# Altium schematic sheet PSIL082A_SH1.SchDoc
size 558 x 431 mm; Date: Not shown in title block; ApprovedBy: Not shown in title block; CheckedBy: Not shown in title block; Author: Not shown in title block; CompanyName: Not shown in title block; Engineer: Not shown in title block; Organization: Not shown in title block; Address1: Not shown in title block; Address2: Not shown in title block; Address3: Not shown in title block; Address4: Not shown in title block; DocumentNumber: 1; Revision: Use project parameter SCH_Rev; SheetNumber: 1; SheetTotal: 2; PageSetup: Record=PageOptions¦CenterHorizontal=True¦CenterVertical=True¦PrintScale=1.00¦XCorrection=1.00¦YCorrection=1.00¦PrintKind=0¦BorderSize=5000000¦LeftOffset=0¦BottomOffset=0¦Orientation=2¦PaperLength=1000¦PaperWidth=1000¦Scale=100¦PaperSource=15¦PrintQuality=600¦MediaType=1¦DitherType=10¦PaperKind=Letter¦PrintScaleMode=1
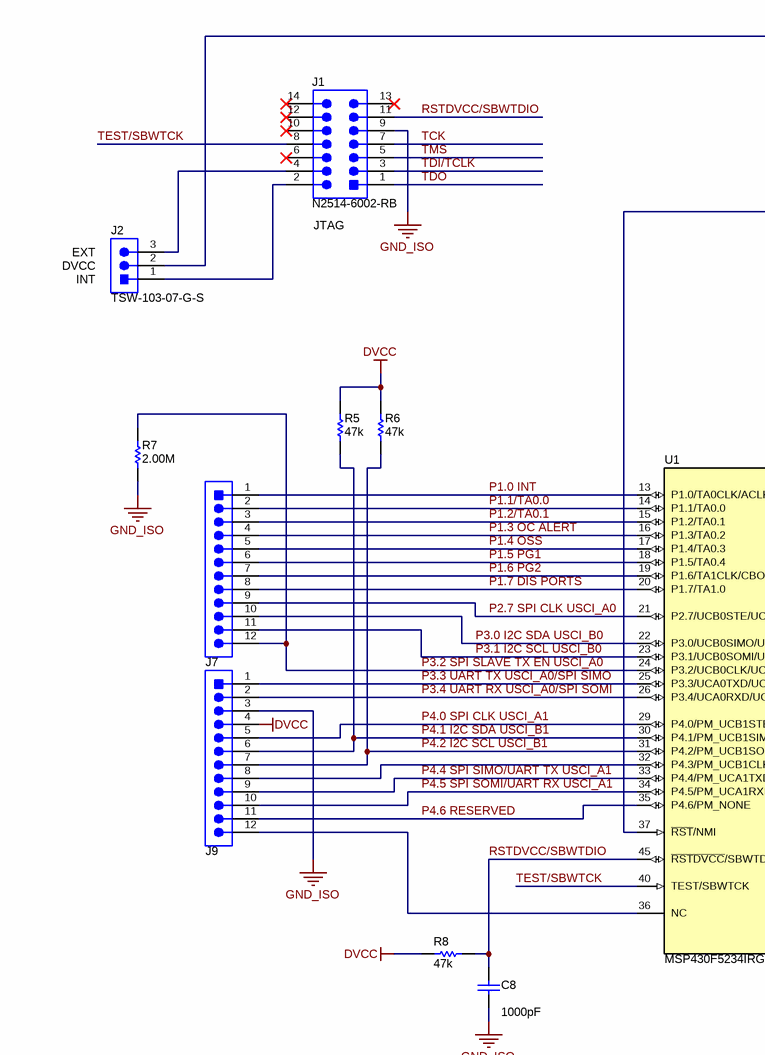
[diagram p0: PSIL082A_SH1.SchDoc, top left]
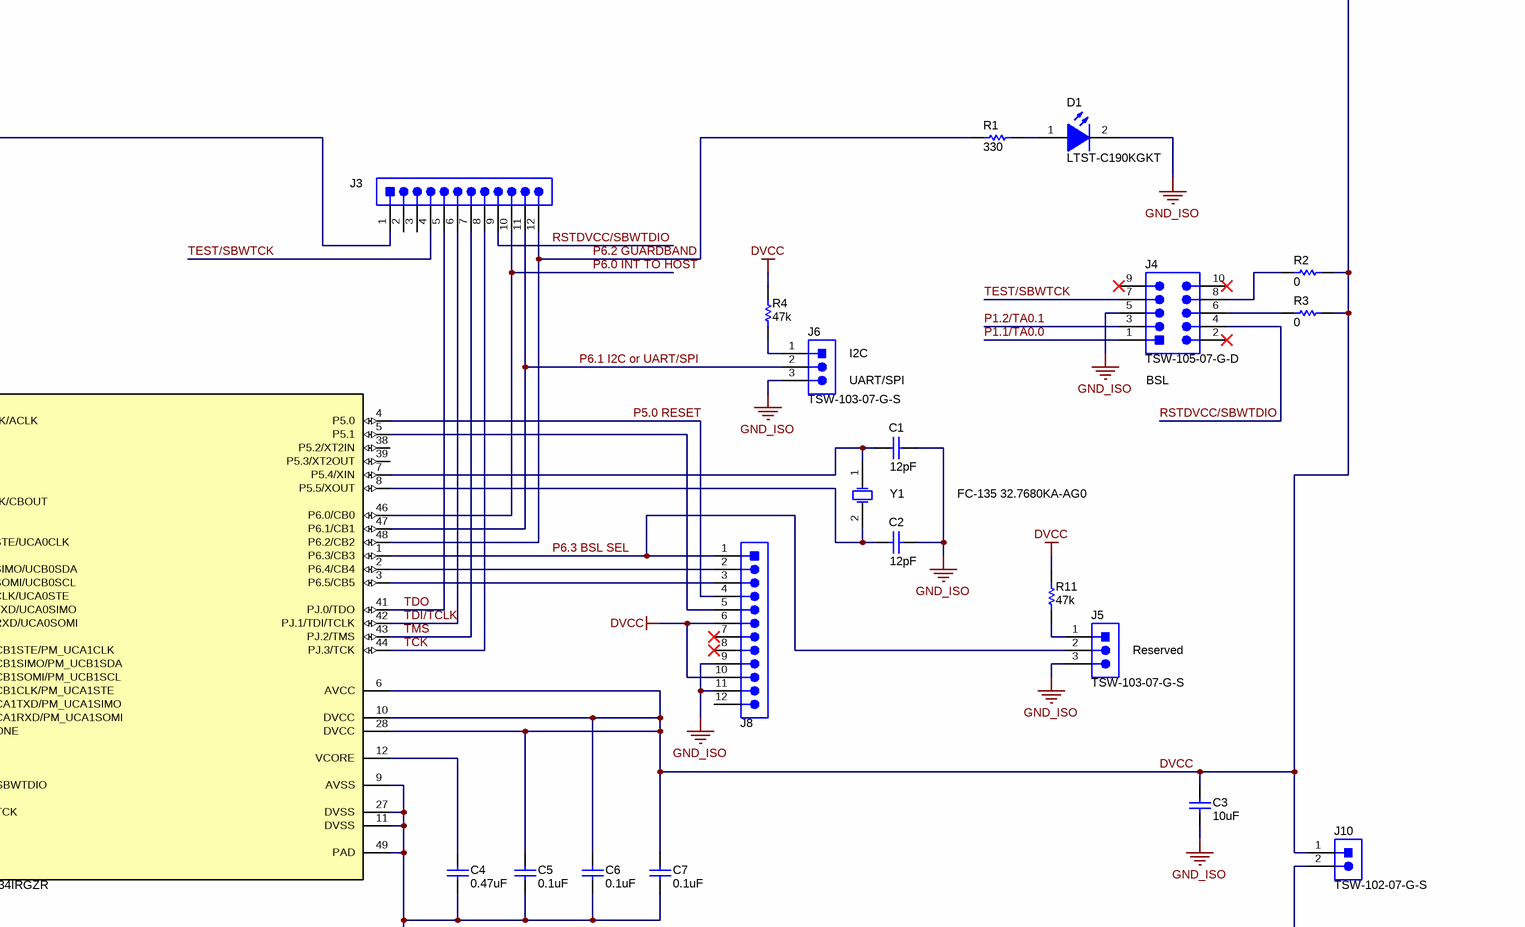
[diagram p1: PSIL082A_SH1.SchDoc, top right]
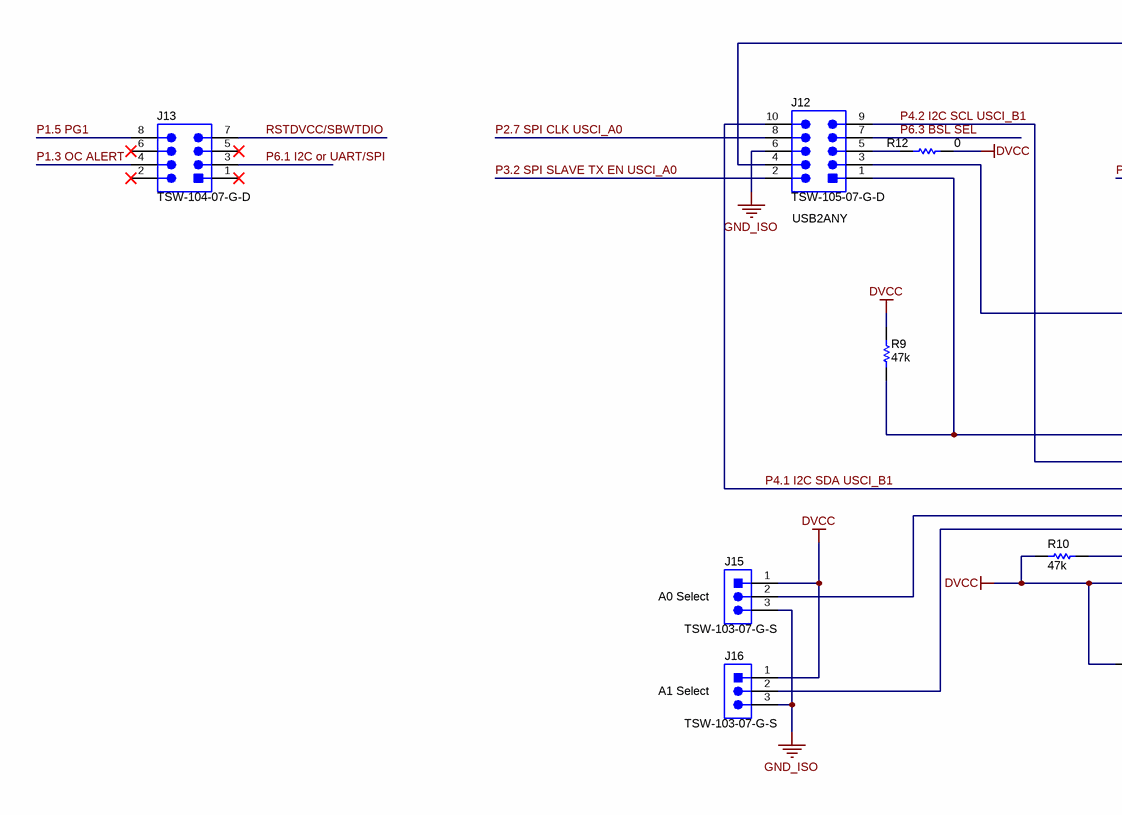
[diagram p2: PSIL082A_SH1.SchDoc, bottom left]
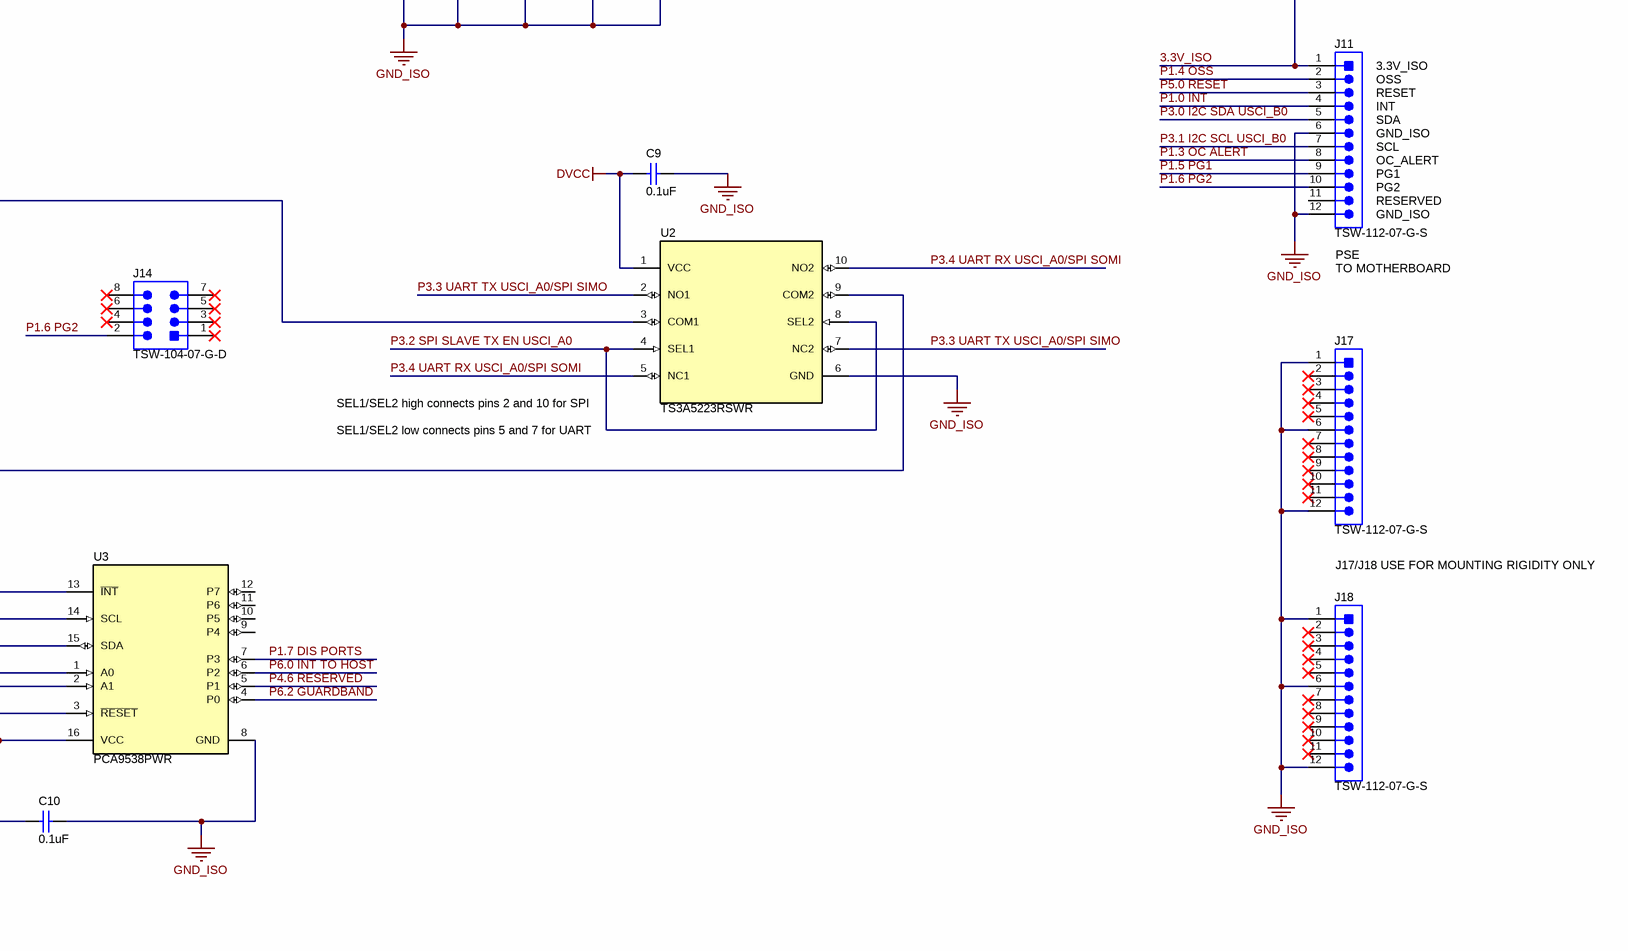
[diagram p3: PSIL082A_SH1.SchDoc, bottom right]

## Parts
C1  ValueDisplayed: 12pF  [0402L]  (hidden comment: CL05C120JB5NNNC)
C2  ValueDisplayed: 12pF  [0402L]  (hidden comment: CL05C120JB5NNNC)
C3  ValueDisplayed: 10uF  [0805L]  (hidden comment: 885012207026)
C4  ValueDisplayed: 0.47uF  [0603L]  (hidden comment: GCM188R71C474KA55D)
C5  ValueDisplayed: 0.1uF  [0603L]  (hidden comment: 885012206046)
C6  ValueDisplayed: 0.1uF  [0603L]  (hidden comment: 885012206046)
C7  ValueDisplayed: 0.1uF  [0603L]  (hidden comment: 885012206046)
C8  ValueDisplayed: 1000pF  [0603L]  (hidden comment: 885012206083)
C9  ValueDisplayed: 0.1uF  [0603L]  (hidden comment: 885012206046)
C10  ValueDisplayed: 0.1uF  [0603L]  (hidden comment: 885012206046)
D1  LTST-C190KGKT  [LED_LTST-C190_G]
J1  N2514-6002-RB  [3M_x2514-60xx]
J2  TSW-103-07-G-S  [TSW-103-07-G-S]
J3  TSW-112-07-G-S  [TSW-112-07-G-S]  (value not drawn)
J4  TSW-105-07-G-D  [TSW-105-07-G-D]
J5  TSW-103-07-G-S  [TSW-103-07-G-S]
J6  TSW-103-07-G-S  [TSW-103-07-G-S]
J7  TSW-112-07-G-S  [TSW-112-07-G-S]  (value not drawn)
J8  TSW-112-07-G-S  [TSW-112-07-G-S]  (value not drawn)
J9  TSW-112-07-G-S  [TSW-112-07-G-S]  (value not drawn)
J10  TSW-102-07-G-S  [TSW-102-07-G-S]
J11  TSW-112-07-G-S  [TSW-112-07-G-S]
J12  TSW-105-07-G-D  [TSW-105-07-G-D]
J13  TSW-104-07-G-D  [TSW-104-07-G-D]
J14  TSW-104-07-G-D  [TSW-104-07-G-D]
J15  TSW-103-07-G-S  [TSW-103-07-G-S]
J16  TSW-103-07-G-S  [TSW-103-07-G-S]
J17  TSW-112-07-G-S  [TSW-112-07-G-S]
J18  TSW-112-07-G-S  [TSW-112-07-G-S]
R1  ValueDisplayed: 330  [0402L]  (hidden comment: CRCW0402330RJNED)
R2  ValueDisplayed: 0  [0402L]  (hidden comment: ERJ-2GE0R00X)
R3  ValueDisplayed: 0  [0402L]  (hidden comment: ERJ-2GE0R00X)
R4  ValueDisplayed: 47k  [0402L]  (hidden comment: CRCW040247K0JNED)
R5  ValueDisplayed: 47k  [0402L]  (hidden comment: CRCW040247K0JNED)
R6  ValueDisplayed: 47k  [0402L]  (hidden comment: CRCW040247K0JNED)
R7  ValueDisplayed: 2.00M  [0402L]  (hidden comment: CRCW04022M00FKED)
R8  ValueDisplayed: 47k  [0402L]  (hidden comment: CRCW040247K0JNED)
R9  ValueDisplayed: 47k  [0402L]  (hidden comment: CRCW040247K0JNED)
R10  ValueDisplayed: 47k  [0402L]  (hidden comment: CRCW040247K0JNED)
R11  ValueDisplayed: 47k  [0402L]  (hidden comment: CRCW040247K0JNED)
R12  ValueDisplayed: 0  [0402L]  (hidden comment: ERJ-2GE0R00X)
U1  MSP430F5234IRGZR  [RGZ0048A]
U2  TS3A5223RSWR  [RSW0010A]
U3  PCA9538PWR  [PW0016A_L]
Y1  FC-135 32.7680KA-AG0  [Epson_FC-135]

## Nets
DVCC: C3.2 C5.2 C6.2 C7.2 C9.2 C10.2 J2.2 J8.6 J8.10 J9.4 J10.1 J15.1 J16.1 R2.1 R3.1 R4.2 R5.2 R6.2 R8.1 R9.2 R10.2 R11.2 R12.1 U1.6(AVCC) U1.10(DVCC) U1.28(DVCC) U2.1(VCC) U3.16(VCC)
GND_ISO: C1.1 C2.1 C3.1 C4.1 C5.1 C6.1 C7.1 C8.2 C9.1 C10.1 D1.2(K) J1.9 J4.5 J5.3 J6.3 J8.9 J8.11 J9.3 J11.6 J11.12 J12.6 J15.3 J16.3 J17.1 J17.6 J17.12 J18.1 J18.6 J18.12 R7.2 U1.9(AVSS) U1.11(DVSS) U1.27(DVSS) U1.49(PAD) U2.6(GND) U3.8(GND)
3.3V_ISO: J10.2 J11.1
P1.0 INT: J7.1 J11.4 U1.13(P1.0/TA0CLK/ACLK)
P1.1/TA0.0: J4.1 J7.2 U1.14(P1.1/TA0.0)
P1.2/TA0.1: J4.3 J7.3 U1.15(P1.2/TA0.1)
P1.3 OC ALERT: J7.4 J11.8 J13.4 U1.16(P1.3/TA0.2)
P1.4 OSS: J7.5 J11.2 U1.17(P1.4/TA0.3)
P1.5 PG1: J7.6 J11.9 J13.8 U1.18(P1.5/TA0.4)
P1.6 PG2: J7.7 J11.10 J14.2 U1.19(P1.6/TA1CLK/CBOUT)
P1.7 DIS PORTS: J7.8 U1.20(P1.7/TA1.0) U3.7(P3)
P2.7 SPI CLK USCI_A0: J7.9 J12.8 U1.21(P2.7/UCB0STE/UCA0CLK)
P3.0 I2C SDA USCI_B0: J7.10 J11.5 U1.22(P3.0/UCB0SIMO/UCB0SDA)
P3.1 I2C SCL USCI_B0: J7.11 J11.7 U1.23(P3.1/UCB0SOMI/UCB0SCL)
P3.2 SPI SLAVE TX EN USCI_A0: J7.12 J12.2 R7.1 U1.24(P3.2/UCB0CLK/UCA0STE) U2.4(SEL1) U2.8(SEL2)
P3.3 UART TX USCI_A0/SPI SIMO: J9.1 U1.25(P3.3/UCA0TXD/UCA0SIMO) U2.2(NO1) U2.7(NC2)
P3.4 UART RX USCI_A0/SPI SOMI: J9.2 U1.26(P3.4/UCA0RXD/UCA0SOMI) U2.5(NC1) U2.10(NO2)
P4.0 SPI CLK USCI_A1: J9.5 U1.29(P4.0/PM_UCB1STE/PM_UCA1CLK)
P4.1 I2C SDA USCI_B1: J9.6 J12.10 R5.1 U1.30(P4.1/PM_UCB1SIMO/PM_UCB1SDA) U3.15(SDA)
P4.2 I2C SCL USCI_B1: J9.7 J12.9 R6.1 U1.31(P4.2/PM_UCB1SOMI/PM_UCB1SCL) U3.14(SCL)
P4.4 SPI SIMO/UART TX USCI_A1: J9.9 U1.33(P4.4/PM_UCA1TXD/PM_UCA1SIMO)
P4.5 SPI SOMI/UART RX USCI_A1: J9.10 U1.34(P4.5/PM_UCA1RXD/PM_UCA1SOMI)
P4.6 RESERVED: J9.11 U1.35(P4.6/PM_NONE) U3.5(P1)
P5.0 RESET: J8.4 J11.3 U1.4(P5.0)
P6.0 INT TO HOST: J3.10 U1.46(P6.0/CB0) U3.6(P2)
P6.1 I2C or UART/SPI: J3.11 J6.2 J13.3 U1.47(P6.1/CB1)
P6.2 GUARDBAND: J3.12 R1.1 U1.48(P6.2/CB2) U3.4(P0)
P6.3 BSL SEL: J5.2 J8.1 J12.7 U1.1(P6.3/CB3)
RSTDVCC/SBWTDIO: C8.1 J1.11 J3.9 J4.4 J13.7 R8.2 U1.45(~{RSTDVCC}/SBWTDIO)
TCK: J1.7 J3.8 U1.44(PJ.3/TCK)
TDI/TCLK: J1.3 J3.6 U1.42(PJ.1/TDI/TCLK)
TDO: J1.1 J3.5 U1.41(PJ.0/TDO)
TEST/SBWTCK: J1.8 J3.4 J4.7 U1.40(TEST/SBWTCK)
TMS: J1.5 J3.7 U1.43(PJ.2/TMS)
NetC1_2: C1.2 U1.7(P5.4/XIN) Y1.1(OSC1)
NetC2_2: C2.2 U1.8(P5.5/XOUT) Y1.2(OSC2)
NetC4_2: C4.2 U1.12(VCORE)
NetD1_1: D1.1(A) R1.2
NetJ1_2: J1.2 J2.1
NetJ1_4: J1.4 J2.3
NetJ3_1: J3.1 U1.37(~{RST}/NMI)
NetJ4_6: J4.6 R3.2
NetJ4_8: J4.8 R2.2
NetJ5_1: J5.1 R11.1
NetJ6_1: J6.1 R4.1
NetJ8_2: J8.2 U1.2(P6.4/CB4)
NetJ8_3: J8.3 U1.3(P6.5/CB5)
NetJ8_5: J8.5 U1.5(P5.1)
NetJ9_8: J9.8 U1.32(P4.3/PM_UCB1CLK/PM_UCA1STE)
NetJ9_12: J9.12 U1.36(NC)
NetJ12_1: J12.1 R9.1 U3.13(~{INT})
NetJ12_3: J12.3 U2.9(COM2)
NetJ12_4: J12.4 U2.3(COM1)
NetJ12_5: J12.5 R12.2
NetJ15_2: J15.2 U3.1(A0)
NetJ16_2: J16.2 U3.2(A1)
NetR10_1: R10.1 U3.3(~{RESET})

Not connected (* = marked no-connect by the designer): J1 6* 10* 12* 13* 14*; J3 2 3; J4 2* 9* 10*; J8 7* 8* 12; J11 11; J13 1* 2* 5* 6*; J14 1* 3* 4* 5* 6* 7* 8*; J17 2* 3* 4* 5* 7* 8* 9* 10* 11*; J18 2* 3* 4* 5* 7* 8* 9* 10* 11*; U1 38(P5.2/XT2IN) 39(P5.3/XT2OUT); U3 9(P4) 10(P5) 11(P6) 12(P7)

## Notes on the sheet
- (near J1) JTAG
- (near J2) EXT
- (near J2) INT
- (near J2) DVCC
- (near J6) I2C
- UART/SPI
- (near J4) BSL
- (near J5) Reserved
- (near J11) 3.3V_ISO
- (near J11) OSS
- (near J11) RESET
- (near J11) INT
- (near J11) SDA
- (near J11) GND_ISO
- (near J11) SCL
- (near J11) OC_ALERT
- (near J11) PG1
- (near J11) PG2
- (near J11) RESERVED
- (near J11) PSE
- (near J11) TO MOTHERBOARD
- (near J12) USB2ANY
- SEL1/SEL2 high connects pins 2 and 10 for SPI
- SEL1/SEL2 low connects pins 5 and 7 for UART
- J17/J18 USE FOR MOUNTING RIGIDITY ONLY
- (near J15) A0 Select
- (near J16) A1 Select

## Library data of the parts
C1 C2 = CMP-0006345-2: CAP, CERM, 12 pF, 50 V, +/- 5%, C0G/NP0, 0402; Manufacturer: Samsung Electro-Mechanics; TaMin_C: -55°C; Polarized: N; SizeAreaWB_mm2: 3; Value1: Unknown; U/M: EA; Value: 12pF; TaMax_C: 125°C; SizeZ_mm: 0.6; SizeX_mm: 1; SizeY_mm: 0.5; Cap_Case: 0402; Value2: 50V; CompType: Capacitor; AEC Category: Q200
C3 = CMP-0007691-2: CAP, CERM, 10 uF, 10 V, +/- 10%, X7R, 0805; Manufacturer: Wurth Elektronik; TaMin_C: -55°C; Polarized: N; SizeAreaWB_mm2: 6.75; Value1: Unknown; U/M: EA; Value: 10uF; TaMax_C: 125°C; SizeZ_mm: 1.45; SizeX_mm: 2; SizeY_mm: 1.25; Cap_Case: 0805; Value2: 10V; SizeArea_mm2: 2.5; CompType: Capacitor; Cap_F: 10µF; AEC Category: Q200
C4 = CMP-0007138-4: CAP, CERM, 0.47 uF, 16 V, +/- 10%, X7R, AEC-Q200 Grade 1, 0603; Manufacturer: MuRata; TaMin_C: -55°C; Polarized: N; SizeAreaWB_mm2: 4.68; Value1: Unknown; U/M: EA; Value: 0.47uF; TaMax_C: 125°C; SizeZ_mm: 1; SizeX_mm: 1.6; SizeY_mm: 0.8; Cap_Case: 0603; Value2: 16V; SizeArea_mm2: 1.28; CompType: Capacitor; AEC Qualified: Y; Cap_F: 470nF; AEC Category: Q200
C5-C7 C9 C10 = CMP-0006829-4: CAP, CERM, 0.1 uF, 16 V, +/- 10%, X7R, 0603; Manufacturer: Wurth Elektronik; TaMin_C: -55°C; Polarized: N; SizeAreaWB_mm2: 4.68; Value1: Unknown; U/M: EA; Value: 0.1uF; TaMax_C: 125°C; SizeZ_mm: 1; SizeX_mm: 1.6; SizeY_mm: 0.8; Cap_Case: 0603; Value2: 16V; SizeArea_mm2: 1.28; CompType: Capacitor; Cap_F: 100nF; AEC Category: Q200
C8 = CMP-0064933-4: CAP, CERM, 1000 pF, 50 V,+/- 10%, X7R, 0603; Manufacturer: Wurth Elektronik; TaMin_C: -55°C; Polarized: N; SizeAreaWB_mm2: 4.68; Value1: Unknown; U/M: EA; Value: 1000pF; TaMax_C: 125°C; SizeZ_mm: 1; SizeX_mm: 1.6; SizeY_mm: 0.8; Cap_Case: 0603; Value2: 50V; SizeArea_mm2: 1.28; CompType: Capacitor; Cap_F: 1nF; AEC Category: Q200
D1 = CMP-0002840-2: LED, Green, SMD; Manufacturer: Lite-On; Value1: W; Io_A: 30mA; Value2: 2V; Tjmax_C: 85°C; Type: AlInGaP
J1 = CMP-0075023-2: Header (shrouded), 100mil, 7x2, Gold, TH; Manufacturer: 3M; Green_Lifecycle: Active; Green_REACh: Passed
J2 J5 J6 J15 J16 = CMP-0075407-2: Header, 100mil, 3x1, Gold, TH; Manufacturer: Samtec; Pitch_mm: 2.54; Cert_VDE: N; Gender: Male; Cert_CSA: Y; Voltage_V: 550V; Green_REACh: Passed; Current_A: 6.3A; Green_Lifecycle: Active; Row_Count: 1
J3 J7-J9 J11 J17 J18 = CMP-0075424-1: Header, 100mil, 12x1, Gold, TH; Manufacturer: Samtec; Pitch_mm: 2.54; Cert_VDE: N; Gender: Male; Cert_CSA: Y; Current_A: 6.3A; Voltage_V: 550V; CT: False; Row_Count: 1; CNHeader: True
J4 = CMP-0075410-2: Header, 100mil, 5x2, Gold, TH; Manufacturer: Samtec; Current_A: 6.3A; Green_Lifecycle: Active; Shrouded: N; Gender: Male; Cert_CSA: Y; Green_REACh: Passed; Voltage_V: 550V; Row_Count: 2; RowSpacing_mm: 2.54
J10 = CMP-0075405-2: Header, 100mil, 2x1, Gold, TH; Manufacturer: Samtec; Pitch_mm: 2.54; Cert_VDE: N; Gender: Male; Cert_CSA: Y; Voltage_V: 550V; Green_REACh: Passed; Current_A: 6.3A; Green_Lifecycle: Active; Row_Count: 1
J12 = CMP-0075410-2: Header, 100mil, 5x2, Gold, TH; Manufacturer: Samtec; Green_Lifecycle: Active; Green_REACh: Passed; Cert_CSA: Y; Cert_CULUS: N; Current_A: 6.3A; Gender: Male; Pitch_mm: 2.54; Row_Count: 2; Voltage_V: 550V
J13 J14 = CMP-0075408-2: Header, 100mil, 4x2, Gold, TH; Manufacturer: Samtec; Pitch_mm: 2.54; Cert_VDE: N; Gender: Male; Cert_CSA: Y; Voltage_V: 550V; Green_REACh: Passed; Current_A: 6.3A; Green_Lifecycle: Active; Row_Count: 2
R1 = CMP-0026906-3: RES, 330, 5%, 0.063 W, AEC-Q200 Grade 0, 0402; Manufacturer: Vishay-Dale; Power_W: 63mW; TempCo: 200 ppm/C; Value_Code: 330R; Value: 330; EIA_Code: E24; SizeX_mm: 1; SizeY_mm: 0.5; SizeZ_mm: 0.6; Value2: 0.063W; CompType: Resistor; AEC Qualified: Y; VDC_V: 50V; AEC Category: Q200; AEC Grade: 0
R2 R3 R12 = CMP-0026992-3: RES, 0, 5%, 0.1 W, AEC-Q200 Grade 0, 0402; Manufacturer: Panasonic; Power_W: 100mW; TempCo: 600 ppm/C; Value_Code: 0000; Value: 0; EIA_Code: E24; SizeX_mm: 1; SizeY_mm: 0.5; SizeZ_mm: 0.6; Value2: 0.1W; AEC Qualified: Y; VDC_V: 50V; AEC Category: Q200; SizeAreaWB_mm2: 3
R4 R8 R11 = CMP-0026935-3: RES, 47 k, 5%, 0.063 W, AEC-Q200 Grade 0, 0402; Manufacturer: Vishay-Dale; Power_W: 63mW; TempCo: 200 ppm/C; Value_Code: 47k0; Value: 47k; EIA_Code: E24; SizeX_mm: 1; SizeY_mm: 0.5; SizeZ_mm: 0.6; Value2: 0.063W; AEC Qualified: Y; VDC_V: 50V; AEC Category: Q200; AEC Grade: 0
R5 R6 R9 R10 = CMP-0026935-3: RES, 47 k, 5%, 0.063 W, AEC-Q200 Grade 0, 0402; Manufacturer: Vishay-Dale; Power_W: 63mW; TempCo: 200 ppm/C; Value_Code: 47k0; Value: 47k; EIA_Code: E24; SizeX_mm: 1; SizeY_mm: 0.5; SizeZ_mm: 0.6; Value2: 0.063W; CompType: Resistor; AEC Qualified: Y; VDC_V: 50V; AEC Category: Q200; AEC Grade: 0
R7 = CMP-0026245-2: RES, 2.00 M, 1%, 0.063 W, AEC-Q200 Grade 0, 0402; Manufacturer: Vishay-Dale; Power_W: 63mW; TempCo: 100 ppm/C; Value_Code: 2M00; Value: 2.00Meg; EIA_Code: E96; Res_ohm: 2M; SizeX_mm: 1; SizeY_mm: 0.5; SizeZ_mm: 0.6; Value2: 0.063W; CompType: Resistor; AEC Qualified: Y; VDC_V: 50V; AEC Category: Q200; AEC Grade: 0
U1 = CMP-0076591-3: Ultra-Low Power MSP430 with 128 KB Flash, RGZ0048A (VQFN-48); Alternate Manufacturer: Texas Instruments; Alternate PartNumber: MSP430F5234IRGZT; SizeY_mm: 7; AEC Category: Q200; CompType: IC; SizeAreaWB_mm2: 81; Rating: Catalog; SizeZ_mm: 1; SizeArea_mm2: 49
U2 = CMP-0085520-1: 0.5Ω Dual SPDT Bidirectional Analog Switch, RSW0010A (UQFN-10); Manufacturer: Texas Instruments; Rating: Catalog; SizeY_mm: 1.8; AEC Qualified: N; SizeZ_mm: 0.55; CompType: IC; SizeArea_mm2: 2.52; AEC Category: Q200; SizeAreaWB_mm2: 6.72; SizeX_mm: 1.4
U3 = CMP-0043202-2: Remote 8-Bit I2C and SMBus Low-Power I/O Expander With Interrupt Output, Reset, and Config Registers, PW0016A (TSSOP-16); Manufacturer: Texas Instruments; AEC Category: Q200; Interrupt Output: Yes; Max Frequency(kHz): 400; VCC(Max)(V): 5.5; fSCLK(Max)(MHz): 0.1, 0.4; Rating: Catalog; CompType: IC; I2C Address: 1110 0xx; AEC Qualified: N; Vcc range(V): 2.3 to 5.5; Technology Family: I2C, SMBus; # of I/Os: 8; VCC(Min)(V): 2.3
Y1 = CMP-0079303-1: Crystal, 32.768 KHz, 20 ppm, 7 pF, SMD; Manufacturer: Epson; TaMin_C: -40°C; Frequency Tolerance: 20 ppm; Load Capacitance: 7 pF; TaMax_C: 85°C; AEC Qualified: N; AEC Category: Q200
